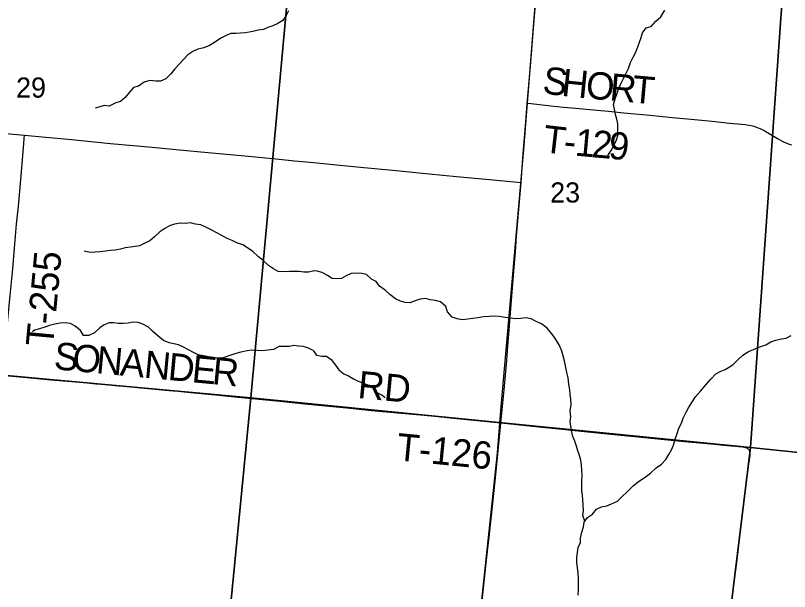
# Model space of a CAD drawing. Extents: x 0 to 1101, y 0 to 440.
# Drawn here: x 840.461 to 842.072, y 372.469 to 373.668 of the extents above; entities that cross this region are included whole.
import ezdxf

# ---------------------------------------------------------------- set-up
doc = ezdxf.new("R2010")
doc.units = 0
for name, color, linetype in [('GM_X_County_Road', 7, 'Continuous'), ('GM_X_Minor_River', 7, 'Continuous'), ('GM_X_Rail_Line', 7, 'Continuous'), ('GM_X_Section', 7, 'Continuous'), ('GM_X_Section_Text', 7, 'Continuous'), ('GM_X_Township_Road', 7, 'Continuous'), ('GM_X_Township_Road_Text', 7, 'Continuous'), ('GM_X_US_Route', 7, 'Continuous')]:
    doc.layers.add(name, color=color, linetype=linetype)

msp = doc.modelspace()

# ---------------------------------------------------------------- linework, layer by layer
at = {"layer": 'GM_X_County_Road'}
for points in [[(839.7575, 373.486), (839.7636, 373.4854), (839.8287, 373.4788), (839.9012, 373.4714), (839.9874, 373.4627), (840.0202, 373.4595), (840.0523, 373.4566), (840.1204, 373.4507), (840.1903, 373.4444), (840.2305, 373.4408), (840.2652, 373.4376), (840.3425, 373.4306), (840.3776, 373.4274), (840.4798, 373.4184)], [(840.4798, 373.4184), (840.5239, 373.4146), (840.5703, 373.4101), (840.6587, 373.4012), (840.7453, 373.3933), (840.8171, 373.3867), (840.847, 373.384), (840.9229, 373.3768), (840.9538, 373.3739), (840.9816, 373.3711), (841.0095, 373.3685), (841.0416, 373.3654), (841.067, 373.363), (841.0948, 373.3603), (841.1294, 373.3568), (841.1863, 373.3513), (841.2462, 373.3456), (841.3217, 373.3382), (841.3792, 373.3327), (841.4553, 373.3254), (841.5132, 373.3198)]]:
    msp.add_lwpolyline(points, dxfattribs=at)
at = {"layer": 'GM_X_Minor_River'}
for points in [[(841.6942, 373.3759), (841.7008, 373.3864), (841.7074, 373.3985), (841.712, 373.4086), (841.7156, 373.42), (841.7149, 373.431), (841.715, 373.442), (841.7125, 373.4515), (841.7099, 373.4617), (841.7077, 373.4727), (841.7059, 373.4822), (841.7086, 373.4924), (841.7133, 373.5056), (841.7169, 373.5162), (841.7215, 373.5264), (841.7312, 373.5464), (841.7367, 373.557), (841.7414, 373.5698), (841.7468, 373.5808), (841.7514, 373.5902), (841.7561, 373.6023), (841.7632, 373.622), (841.7663, 373.6314), (841.7736, 373.642), (841.7839, 373.6449), (841.7939, 373.6554), (841.8039, 373.6648), (841.8124, 373.6788)], [(841.0289, 373.6773), (841.0244, 373.6673), (841.0177, 373.6572), (841.0069, 373.6507), (840.9965, 373.6457), (840.9865, 373.6426), (840.9769, 373.6387), (840.9659, 373.6372), (840.9551, 373.6341), (840.9395, 373.6315), (840.9296, 373.631), (840.9197, 373.6302), (840.9095, 373.6301), (840.8995, 373.6259), (840.8887, 373.6205), (840.8755, 373.6114), (840.8651, 373.6049), (840.8528, 373.6004), (840.8406, 373.5973), (840.8298, 373.5927), (840.8194, 373.5859), (840.8021, 373.5667), (840.7923, 373.5564), (840.7844, 373.546), (840.7738, 373.5357), (840.7631, 373.5307), (840.7528, 373.531), (840.7407, 373.5322), (840.7285, 373.5287), (840.7169, 373.5208), (840.7069, 373.5176), (840.6986, 373.508), (840.6892, 373.4966), (840.6795, 373.4889), (840.6699, 373.4858), (840.6557, 373.4791), (840.6458, 373.4801), (840.6362, 373.4774), (840.6267, 373.4746)], [(841.0824, 373.1366), (841.0711, 373.1337), (841.0613, 373.1338), (841.0514, 373.1352), (841.0412, 373.1348), (841.0313, 373.1351), (841.0203, 373.1343), (841.0078, 373.135), (840.9977, 373.1406), (840.9873, 373.1477), (840.9762, 373.1575), (840.9666, 373.1653), (840.9551, 373.1763), (840.944, 373.1842), (840.9339, 373.1905), (840.9219, 373.1946), (840.9122, 373.1995), (840.9017, 373.2036), (840.889, 373.2104), (840.8785, 373.2163), (840.8684, 373.2216), (840.8572, 373.2272), (840.8464, 373.232), (840.8358, 373.2331), (840.8252, 373.2361), (840.8138, 373.2345), (840.804, 373.2352), (840.7921, 373.2333), (840.7818, 373.2298), (840.7718, 373.2244), (840.7617, 373.2172), (840.7504, 373.2073), (840.7406, 373.1989), (840.7302, 373.1939), (840.7194, 373.1882), (840.7099, 373.1866), (840.7, 373.1857), (840.689, 373.1838), (840.6794, 373.1811), (840.6687, 373.1795), (840.6584, 373.1786), (840.6485, 373.1771), (840.6367, 373.1755), (840.6268, 373.1754), (840.6169, 373.1742), (840.6068, 373.1764), (840.6041, 373.1769)], [(841.6459, 372.6151), (841.6422, 372.6271), (841.6431, 372.6373), (841.6428, 372.6494), (841.6421, 372.6597), (841.6411, 372.6692), (841.64, 372.6794), (841.6401, 372.6892), (841.6399, 372.6991), (841.6407, 372.7105), (841.6397, 372.7218), (841.639, 372.7324), (841.638, 372.7423), (841.6346, 372.7522), (841.6313, 372.7617), (841.6284, 372.7715), (841.625, 372.7818), (841.6209, 372.7913), (841.618, 372.8042), (841.6155, 372.822), (841.6167, 372.8322), (841.6157, 372.8455), (841.6177, 372.8576), (841.6167, 372.8693), (841.6157, 372.8788), (841.6146, 372.889), (841.6128, 372.9004), (841.6114, 372.9137), (841.6089, 372.9247), (841.6034, 372.9493), (841.6012, 372.9596), (841.5979, 372.9694), (841.593, 372.9812), (841.587, 372.9911), (841.5803, 373.0014), (841.5679, 373.017), (841.5561, 373.0262), (841.5448, 373.0309), (841.5342, 373.0366), (841.5239, 373.0382), (841.5125, 373.0372), (841.5026, 373.0366), (841.4908, 373.0378), (841.4805, 373.0394), (841.4679, 373.041), (841.4584, 373.0419), (841.4466, 373.0412), (841.4352, 373.0406), (841.4234, 373.0388), (841.4127, 373.037), (841.4028, 373.036), (841.3906, 373.0342), (841.38, 373.0362), (841.3697, 373.0401), (841.3599, 373.0507), (841.3566, 373.0621), (841.3453, 373.0717), (841.335, 373.0744), (841.324, 373.0761), (841.3145, 373.0784), (841.3031, 373.0774), (841.2927, 373.0741), (841.282, 373.0696), (841.2718, 373.0705), (841.2623, 373.0732), (841.2517, 373.0782), (841.2399, 373.0867), (841.2301, 373.0958), (841.2188, 373.1043), (841.212, 373.1138), (841.2022, 373.1188), (841.1916, 373.1284), (841.1821, 373.1307), (841.1707, 373.1312), (841.1596, 373.1309), (841.1493, 373.1257), (841.1394, 373.1205), (841.1298, 373.1195), (841.1203, 373.12), (841.1105, 373.1265), (841.0995, 373.1326), (841.0889, 373.1354), (841.0822, 373.1366)], [(841.0803, 372.9703), (841.0698, 372.9759), (841.06, 372.9785), (841.0498, 372.9795), (841.04, 372.9806), (841.0304, 372.979), (841.0191, 372.9789), (841.0096, 372.9785), (840.998, 372.9728), (840.9869, 372.9712), (840.974, 372.9701), (840.9642, 372.9707), (840.9532, 372.9711), (840.9429, 372.9695), (840.9303, 372.9672), (840.9196, 372.9641), (840.9069, 372.96), (840.8954, 372.9558), (840.8843, 372.9538), (840.8726, 372.9557), (840.8624, 372.9575), (840.8526, 372.9597), (840.8409, 372.9615), (840.8312, 372.966), (840.8208, 372.972), (840.811, 372.9772), (840.8002, 372.9824), (840.7904, 372.9846), (840.7806, 372.9864), (840.7693, 372.9913), (840.7578, 373.0003), (840.7471, 373.0101), (840.7375, 373.019), (840.7263, 373.0254), (840.7166, 373.0287), (840.7052, 373.0295), (840.6957, 373.0271), (840.6846, 373.027), (840.6752, 373.0269), (840.6653, 373.028), (840.6558, 373.0283), (840.6458, 373.024), (840.6362, 373.0175), (840.6256, 373.0072), (840.6133, 373.0019), (840.6027, 373.0019), (840.5961, 373.0119), (840.585, 373.0209), (840.5753, 373.0265), (840.5644, 373.028), (840.5541, 373.0275), (840.543, 373.0252), (840.532, 373.0225), (840.522, 373.019), (840.5109, 373.0156), (840.5002, 373.0125), (840.4963, 373.0092)], [(841.6319, 372.4611), (841.6332, 372.4725), (841.6329, 372.4865), (841.633, 372.496), (841.632, 372.507), (841.6309, 372.5192), (841.6295, 372.529), (841.6296, 372.5397), (841.6305, 372.5499), (841.6325, 372.5609), (841.6367, 372.5707), (841.6372, 372.5801), (841.6396, 372.5926), (841.6431, 372.6036), (841.6444, 372.6131), (841.6517, 372.6228), (841.6621, 372.6303), (841.6701, 372.6405), (841.6805, 372.6449), (841.6915, 372.6471), (841.7015, 372.6512), (841.7137, 372.6571), (841.7241, 372.6665), (841.7341, 372.6766), (841.7464, 372.6886), (841.7579, 372.6976), (841.7713, 372.7066), (841.7828, 372.7152), (841.7947, 372.7264), (841.8054, 372.7343), (841.8147, 372.744), (841.8212, 372.7538), (841.8263, 372.764), (841.8309, 372.7738), (841.8333, 372.7836), (841.8384, 372.798), (841.8415, 372.8089), (841.847, 372.8191), (841.8505, 372.83), (841.8571, 372.8421), (841.8621, 372.8515), (841.8691, 372.8624), (841.8764, 372.8741), (841.8868, 372.8861), (841.8984, 372.9), (841.908, 372.9109), (841.9184, 372.9218), (841.9279, 372.9266), (841.9379, 372.931), (841.9543, 372.9404), (841.9655, 372.952), (841.9751, 372.961), (841.987, 372.9681), (841.9973, 372.9729), (842.0103, 372.9784), (842.0225, 372.9821), (842.0332, 372.9888), (842.0435, 372.9921), (842.0554, 372.9947), (842.0649, 372.9965), (842.0752, 373.0017)], [(841.0803, 372.9703), (841.0876, 372.9606), (841.0986, 372.959), (841.1081, 372.9589), (841.1183, 372.9516), (841.127, 372.9402), (841.1341, 372.9306), (841.1447, 372.9218), (841.1542, 372.9176), (841.1644, 372.9118), (841.1743, 372.9068), (841.1837, 372.9029), (841.1936, 372.899), (841.2035, 372.8933), (841.2133, 372.8833), (841.2239, 372.8776), (841.2307, 372.873)]]:
    msp.add_lwpolyline(points, dxfattribs=at)
at = {"layer": 'GM_X_Rail_Line'}
msp.add_lwpolyline([(841.0634, 368.7492), (841.0752, 368.8127), (841.0841, 368.8787), (841.1281, 369.2523), (841.1581, 369.5196), (841.193, 369.8378), (841.2158, 370.1274), (841.272, 370.836), (841.3678, 371.852), (841.4644, 372.7575), (841.4712, 372.8458), (841.5195, 373.3971), (841.577, 374.1201)], dxfattribs=at)
at = {"layer": 'GM_X_Section'}
for points in [[(840.0284, 373.9679), (841.0424, 373.8729), (840.951, 372.8721), (839.9098, 372.9668)], [(841.0424, 373.8729), (842.0616, 373.7703), (841.9909, 372.7687), (840.951, 372.8721)], [(842.0616, 373.7703), (843.1376, 373.6589), (843.0306, 372.6604), (841.9909, 372.7687)], [(840.951, 372.8721), (840.8555, 371.8964), (839.8051, 371.9893), (839.9098, 372.9668)], [(840.951, 372.8721), (841.9909, 372.7687), (841.873, 371.8071), (840.8555, 371.8964)], [(843.0306, 372.6604), (842.9284, 371.7073), (841.873, 371.8071), (841.9909, 372.7687)]]:
    msp.add_lwpolyline(points, close=True, dxfattribs=at)
at = {"layer": 'GM_X_Township_Road'}
for points in [[(841.5263, 373.4851), (841.5343, 373.4842), (841.575, 373.4798), (841.6016, 373.477), (841.6263, 373.4747), (841.6715, 373.4706), (841.6956, 373.4683), (841.7204, 373.4658), (841.742, 373.4638), (841.7742, 373.4607), (841.8286, 373.4555), (841.8744, 373.4512), (841.9114, 373.4474), (841.9473, 373.4438), (841.9721, 373.4417), (841.9795, 373.4408), (841.9836, 373.4402), (841.988, 373.4393), (841.9925, 373.4384), (841.9977, 373.437), (842.0071, 373.4338), (842.0105, 373.4323), (842.0149, 373.4303), (842.0195, 373.428), (842.0297, 373.4221), (842.0471, 373.4113), (842.0565, 373.406), (842.0611, 373.4038), (842.0662, 373.4017), (842.0713, 373.3999), (842.0765, 373.3981)], [(840.4325, 372.9183), (840.4367, 372.9558), (840.4402, 372.9873), (840.4437, 373.0207), (840.4499, 373.085), (840.4551, 373.1407), (840.4588, 373.1834), (840.4633, 373.2333), (840.4669, 373.2711), (840.4697, 373.3022), (840.4718, 373.3263), (840.4784, 373.4006), (840.4793, 373.4117), (840.4798, 373.4184)], [(841.4715, 372.8193), (841.4633, 372.8201), (841.3799, 372.8284), (841.3329, 372.8329), (841.3118, 372.835), (841.2561, 372.8402), (841.2023, 372.8452), (841.1504, 372.8504), (841.0842, 372.857), (841.0564, 372.8598), (841.0113, 372.8642), (840.9674, 372.8686), (840.9167, 372.8735), (840.8771, 372.8774), (840.832, 372.8818), (840.7986, 372.8851), (840.7807, 372.8869), (840.7219, 372.8924), (840.694, 372.8948), (840.668, 372.8972), (840.6482, 372.8989), (840.6284, 372.9007), (840.6031, 372.9029), (840.5345, 372.9087), (840.4849, 372.9134), (840.4388, 372.9177)], [(841.9521, 372.4501), (841.9549, 372.4727), (841.9616, 372.5238), (841.965, 372.552), (841.9694, 372.5896), (841.9728, 372.6173), (841.9758, 372.6407), (841.9792, 372.6681), (841.9825, 372.6993), (841.9841, 372.7123), (841.9859, 372.7251), (841.9887, 372.7431), (841.9899, 372.7522), (841.9901, 372.7541), (841.9902, 372.7556), (841.9903, 372.757), (841.9902, 372.7582), (841.99, 372.7593), (841.9897, 372.7603), (841.9895, 372.7611), (841.9891, 372.7618), (841.9885, 372.7628), (841.9878, 372.7637), (841.9871, 372.7646), (841.9864, 372.7653), (841.9854, 372.7661), (841.9846, 372.7667), (841.9834, 372.7674), (841.9821, 372.7679), (841.9809, 372.7683), (841.9792, 372.7688), (841.9778, 372.7691), (841.976, 372.7694), (841.9742, 372.7697), (841.9709, 372.77), (841.9658, 372.7704), (841.935, 372.7729), (841.9158, 372.7746), (841.8774, 372.7782), (841.8533, 372.7806), (841.7841, 372.7876), (841.7068, 372.7952), (841.6382, 372.8021), (841.5986, 372.806), (841.5362, 372.8126), (841.4715, 372.8193)]]:
    msp.add_lwpolyline(points, dxfattribs=at)
at = {"layer": 'GM_X_US_Route'}
for points in [[(841.5132, 373.3198), (841.5179, 373.3802), (841.5238, 373.4545), (841.5263, 373.4851), (841.5269, 373.4916), (841.5335, 373.5707), (841.5399, 373.6495), (841.5432, 373.6904)], [(841.429, 372.4171), (841.4402, 372.5215), (841.4436, 372.553), (841.4466, 372.582), (841.4515, 372.6265), (841.4598, 372.7056), (841.4715, 372.8193), (841.4781, 372.8884), (841.4835, 372.9498), (841.485, 372.9703), (841.4942, 373.0836), (841.4985, 373.1356), (841.5016, 373.1759), (841.504, 373.2081), (841.5132, 373.3198)]]:
    msp.add_lwpolyline(points, dxfattribs=at)

# ---------------------------------------------------------------- texts
at = {"layer": 'GM_X_Section_Text'}
for s, p in [('29', (840.4622, 373.4967)), ('23', (841.5739, 373.2784))]:
    msp.add_text(s, height=0.04186, rotation=0, dxfattribs=at).set_placement(p)
at = {"layer": 'GM_X_Township_Road_Text'}
for s, height, rotation, p in [('S', 0.0568, 352.4713, (841.5562, 373.5059)), ('H', 0.0568, 354.1197, (841.596, 373.5006)), ('O', 0.0568, 354.8154, (841.6465, 373.4954)), ('R', 0.0568, 354.8301, (841.6963, 373.4909)), ('T', 0.0568, 354.8307, (841.7428, 373.4867)), ('T', 0.0568, 353.4284, (841.5571, 373.3834)), ('1', 0.0568, 354.7276, (841.6239, 373.3762)), ('2', 0.0568, 354.8658, (841.6589, 373.3729)), ('9', 0.0568, 354.8994, (841.6938, 373.3698)), ('-', 0.0568, 354.4695, (841.6004, 373.3784)), ('T-255', 0.05682, 84.6787, (840.5388, 372.9771)), ('S', 0.0568, 354.6038, (840.5394, 372.9318)), ('O', 0.0568, 354.6008, (840.5775, 372.9282)), ('N', 0.0568, 354.6012, (840.6273, 372.9235)), ('A', 0.0568, 354.6049, (840.6771, 372.9188)), ('N', 0.0568, 354.6008, (840.7269, 372.9141)), ('D', 0.0568, 354.6029, (840.7767, 372.9094)), ('E', 0.0568, 354.6007, (840.8264, 372.9047)), ('R', 0.0568, 354.5904, (840.8687, 372.9007)), ('RD', 0.05682, 354.5823, (841.1718, 372.8718)), ('T-126', 0.05682, 354.4276, (841.2525, 372.7423))]:
    msp.add_text(s, height=height, rotation=rotation, dxfattribs=at).set_placement(p)

doc.saveas('drawing.dxf')
